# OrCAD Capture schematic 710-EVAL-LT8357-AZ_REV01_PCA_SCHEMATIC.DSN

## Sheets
1 PAGE1
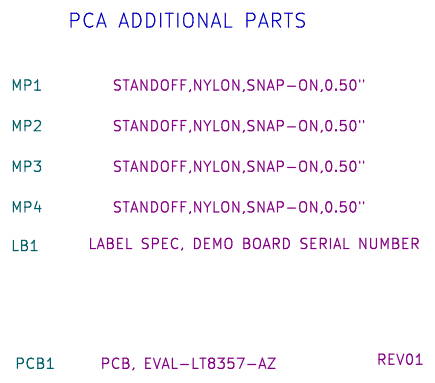
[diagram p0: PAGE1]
2 LT8357EMSE: size Custom; note: 60V LOW-IQ BOOST CONTROLLER
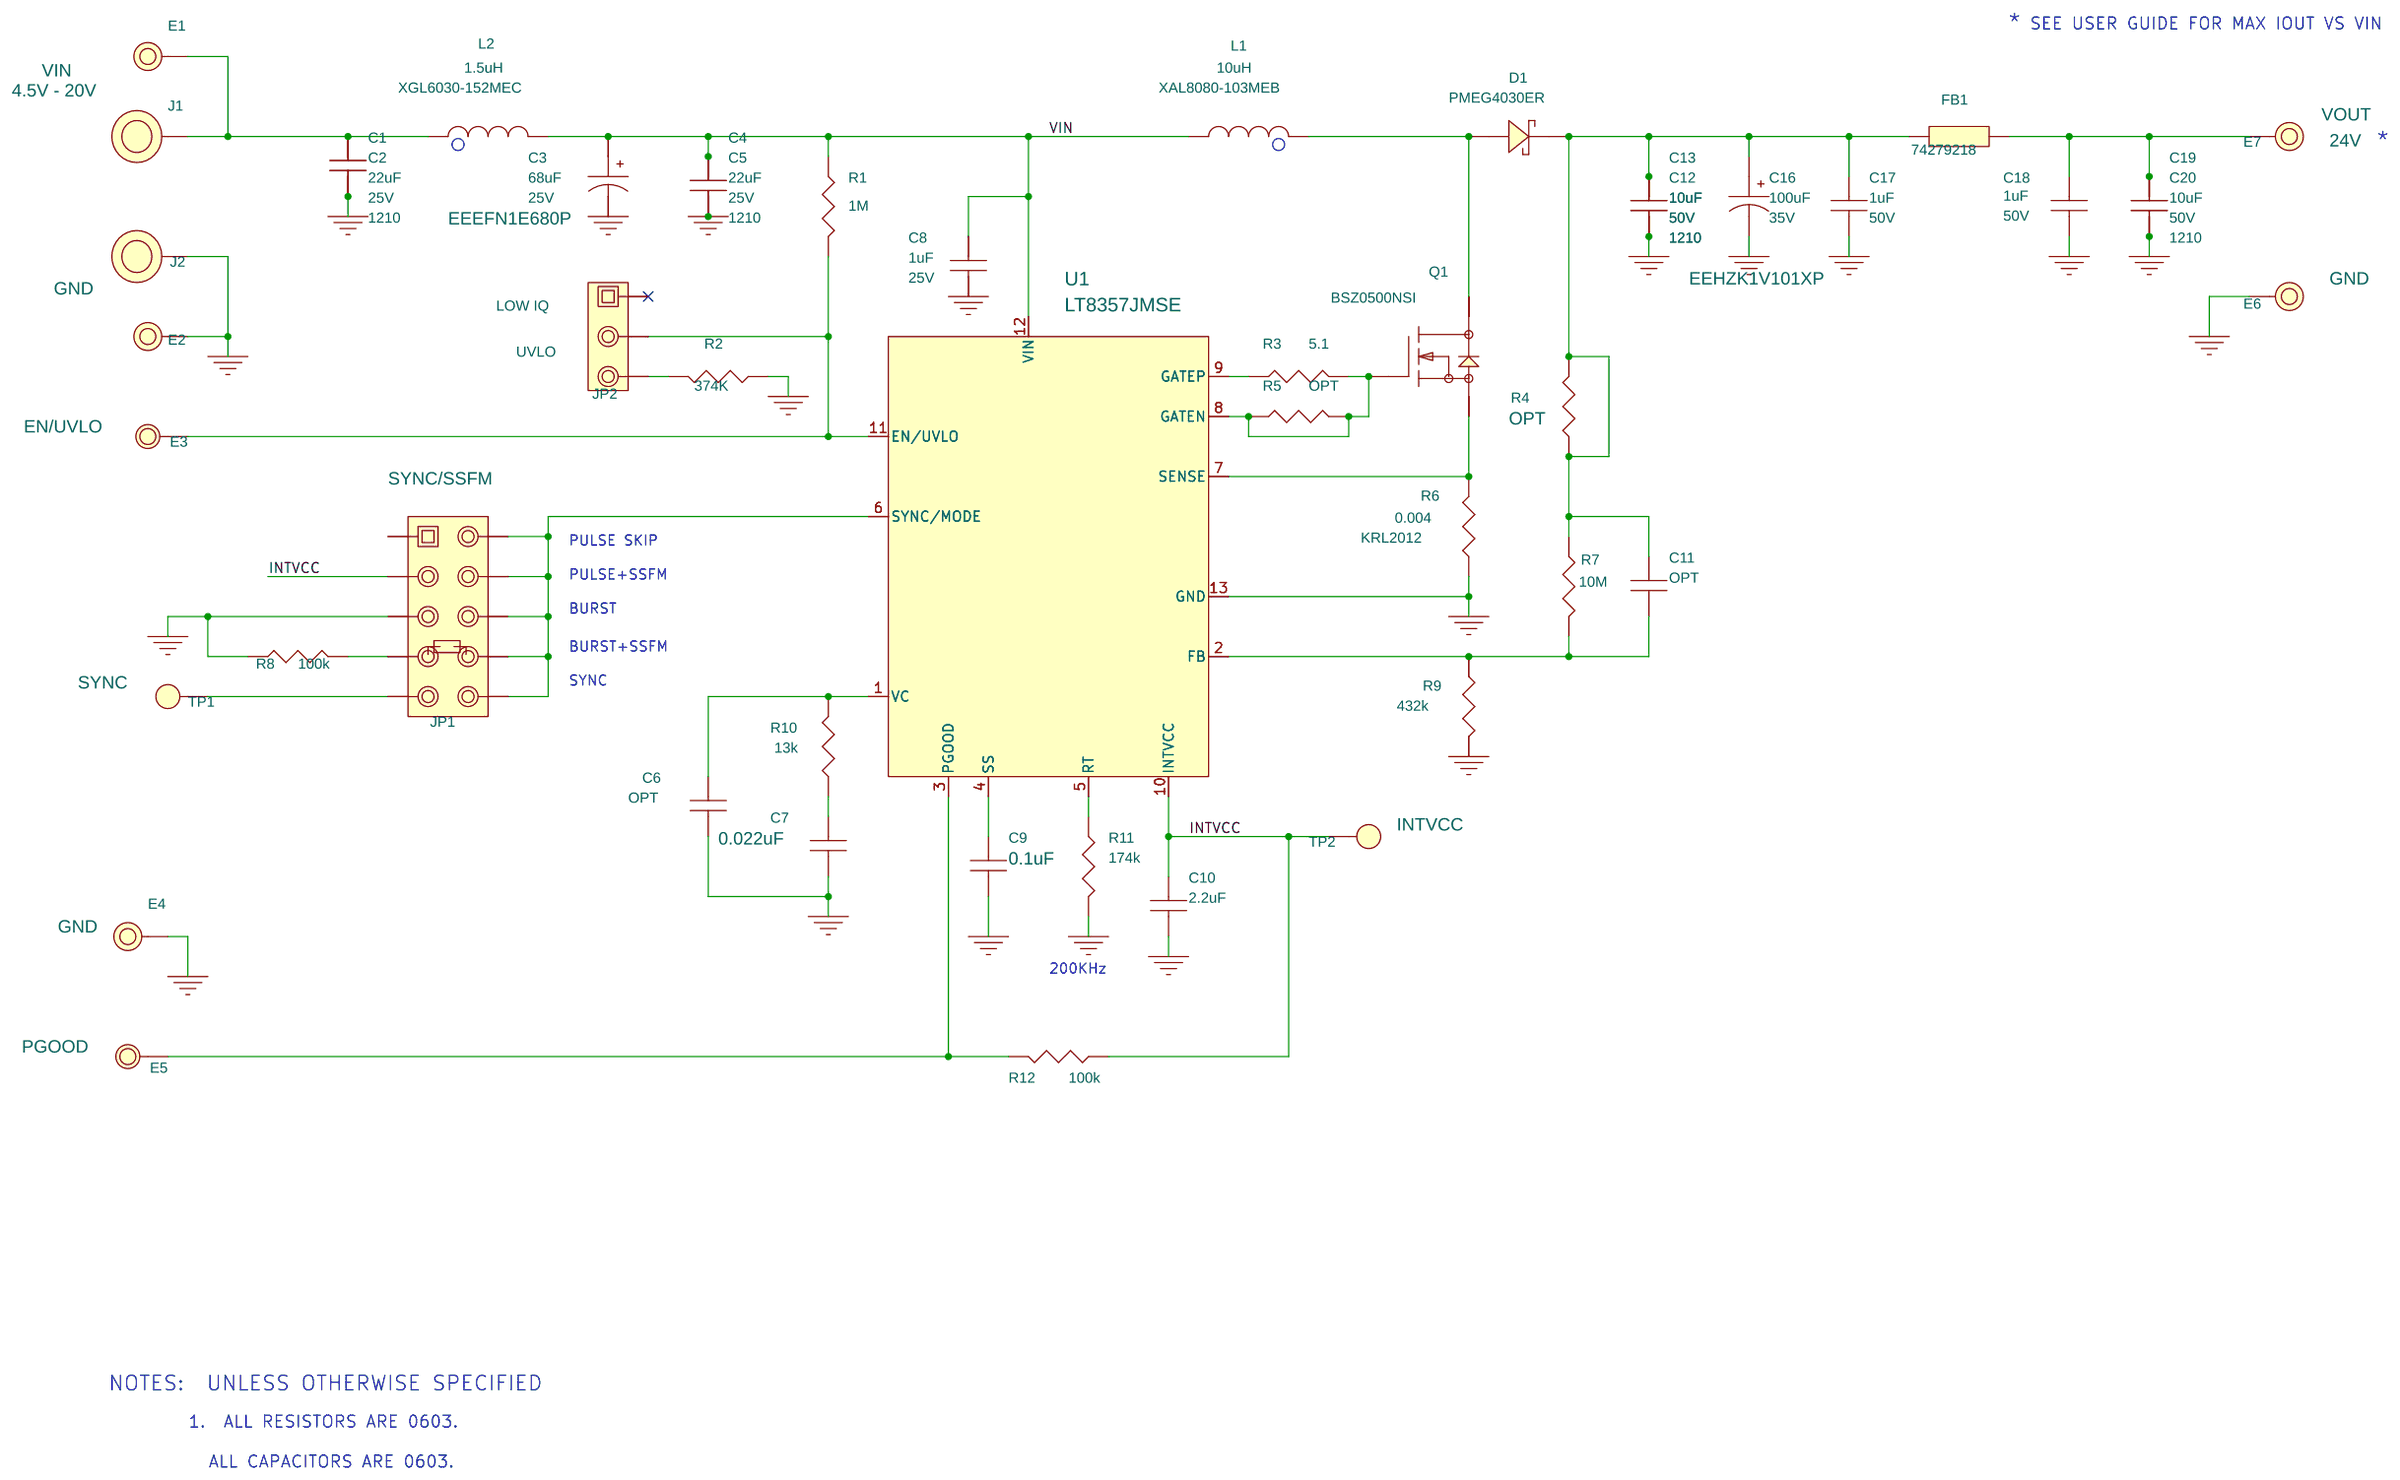
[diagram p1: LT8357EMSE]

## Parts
sheet LT8357EMSE
C1  22uF  [CC1210N]
C2  22uF  [CC1210N]
C3  68uF  [PANASONIC_FN_6.3X5.8]
C4  22uF  [CC1210N]
C5  22uF  [CC1210N]
C6  OPT  [CC0603N]
C7  0.022uF  [CC0603N]
C8  1uF  [CC0603N]
C9  0.1uF  [CC0603N]
C10  2.2uF  [CC0603N]
C11  OPT  [CC0603N]
C12  10uF  [CC1210N]
C13  10uF  [CC1210N]
C16  100uF  [PANASONIC_ZK_6.3X7.7]
C17  1uF  [CC0603N]
C18  1uF  [CC0603N]
C19  10uF  [CC1210N]
C20  10uF  [CC1210N]
D1  PMEG4030ER  [SOD-123W-N]
E1  TEST POINT  [MILLMAX2501]
E2  TEST POINT  [MILLMAX2501]
E3  TEST POINT  [MILLMAX2308]
E4  TEST POINT  [MILLMAX2501]
E5  TEST POINT  [MILLMAX2308]
E6  TEST POINT  [MILLMAX2501]
E7  TEST POINT  [MILLMAX2501]
FB1  600 OHMS @100MHz  [IND1206N]
J1  BANANA JACK  [KEY-575-4]
J2  BANANA JACK  [KEY-575-4]
JP1  HDR  [HD2X5-079]
JP2  HDR.  [HD1X3-079]
L1  10uH  [COILCRAFT-XAL8080]
L2  1.5uH  [COILCRAFT-XGL6030]
Q1  BSZ0500NSI  [INFINEON-PG-TSDSON-8-FL]
R1  1M  [CR0603N]
R2  374K  [CR0603N]
R3  5.1  [CR0603N]
R4  OPT  [CR0603N]
R5  OPT  [CR0603N]
R6  0.004  [SUSUMU-KRL2012]
R7  10M  [CR0603N]
R8  100k  [CR0603N]
R9  432k  [CR0603N]
R10  13k  [CR0603N]
R11  174k  [CR0603N]
R12  100k  [CR0603N]
TP1  TEST PAD  [PADSTYLE1]
TP2  TEST PAD  [PADSTYLE1]
U1  LT8357JMSE  [LTC-MSOP-12-1666]
XJP1  SHUNT
XJP2  SHUNT
sheet PAGE1
LB1  LABEL  [895-0154_REV01]
MP1  STANDOFF  [KEYSTONE_8829-8834]
MP2  STANDOFF  [KEYSTONE_8829-8834]
MP3  STANDOFF  [KEYSTONE_8829-8834]
MP4  STANDOFF  [KEYSTONE_8829-8834]
PCB1  PCB, EVAL-LT8357-AZ

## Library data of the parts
C1 C2 C4 C5 = CAP: CAP.,22uF,X7R,25V,20%,1210,AEC-Q200; CLASS: DISCRETE; Dielectric Type: X7R; FPLIST: CC1210N,CC1210L,CC1210M; Inventory Qty: 2730; Manufacturer: TAIYO YUDEN; Manufacturer PN: TMK325B7226MMHP; PART_NUMBER: 150-1664; Package Size: 1210; Rated Voltage: 25V; Tolerance: 20%
C3 = CAP_P_ALT: CAP.,68uF,ALUM ELECT,25V,20%,6.3x5.8mm,RADIAL,SMD,AEC-Q200; CLASS: DISCRETE; Dielectric Type: ALUM ELECT; FPLIST: PANASONIC_FN_6.3X5.8,PANASONIC_FN_6-3X5-8; Inventory Qty: 0; Manufacturer: PANASONIC; Manufacturer PN: EEEFN1E680P; PART_NUMBER: 150-1872; Package Size: 6.3x5.8mm,RADIAL,SMD; Package Type: Surface Mount; Rated Voltage: 25V; Tolerance: 20%
C6 = CAP: CAP., OPTION, 0603; 1ST FIELD PART: TBD; CLASS: DISCRETE; FPLIST: CC0603N,CC0603L,CC0603M; PART_NUMBER: 150-3038; Package Size: 0603; Package Type: SMD
C7 = CAP: CAP.,0.022uF,X7R,25V,10%,0603,AEC-Q200; CLASS: DISCRETE; Dielectric Type: X7R; FPLIST: CC0603N,CC0603L,CC0603M; Inventory Qty: 0; Manufacturer: KEMET; Manufacturer PN: C0603C223K3RACAUTO; PART_NUMBER: 150-1867; Package Size: 0603; Rated Voltage: 25V; Tolerance: 10%
C8 = CAP: CAP.,1uF,X7R,25V,10%,0603,AEC-Q200; CLASS: DISCRETE; Dielectric Type: X7R; FPLIST: CC0603N,CC0603L,CC0603M; Inventory Qty: 53700; Manufacturer: MURATA; Manufacturer PN: GCM188R71E105KA64D; PART_NUMBER: 150-0291; Package Size: 0603; Rated Voltage: 25V; Tolerance: 10%
C9 = CAP: CAP.,0.1uF,X7R,50V,10%,0603,AEC-Q200; 1ST FIELD PART: TBD; CLASS: DISCRETE; Dielectric Type: X7R; FPLIST: CC0603N,CC0603L,CC0603M; Inventory Qty: 20275; Manufacturer: TDK; Manufacturer PN: CGA3E2X7R1H104K080AA; PART_NUMBER: 150-0514; Package Size: 0603; Rated Voltage: 50V; Tolerance: 10%
C10 = CAP: CAP.,2.2uF,X5R,16V,10%,0603,AEC-Q200; CLASS: DISCRETE; Dielectric Type: X5R; FPLIST: CC0603N,CC0603L,CC0603M; Inventory Qty: 0; Manufacturer: TAIYO YUDEN; Manufacturer PN: EMK107ABJ225KAHT; PART_NUMBER: 150-1868; Package Size: 0603; Package Type: SMD; Rated Voltage: 16V; Temperature Coefficient: X5R; Tolerance: 10%
C11 = CAP: CAP., OPTION, 0603; CLASS: DISCRETE; FPLIST: CC0603N,CC0603L,CC0603M; PART_NUMBER: 150-3038; Package Size: 0603; Package Type: SMD
C12 C13 C19 C20 = CAP: CAP.,10uF,X7S,50V,10%,1210,AEC-Q200, NO SUBS ALLOWED; CLASS: DISCRETE; Dielectric Type: X7S; FPLIST: CC1210N,CC1210L,CC1210M; Inventory Qty: 10520; Manufacturer: MURATA; Manufacturer PN: GCM32EC71H106KA03L; PART_NUMBER: 150-2354; Package Size: 1210; Rated Voltage: 50V; Tolerance: 10%
C16 = CAP_P_ALT: CAP.,100uF,ALUM,35V,20%,SMD,AEC-Q200; CLASS: DISCRETE; Dielectric Type: ALUM; FPLIST: PANASONIC_ZK_6.3X7.7,PANASONIC_ZK_6-3X7-7; Inventory Qty: 0; Manufacturer: PANASONIC; Manufacturer PN: EEHZK1V101XP; PART_NUMBER: 150-1440; Package Size: SMD; Rated Voltage: 35V; Tolerance: 20%
C17 C18 = CAP: CAP.,1uF,X5R,50V,10%,0603,AEC-Q200; CLASS: DISCRETE; Dielectric Type: X5R; FPLIST: CC0603N,CC0603L,CC0603M; Inventory Qty: 52068; Manufacturer: TAIYO YUDEN; Manufacturer PN: UMK107ABJ105KAHT; PART_NUMBER: 150-2446; Package Size: 0603; Package Type: SMD; Rated Voltage: 50V; Tolerance: 10%
D1 = DIODE_SCHOTTKY_A_ALT: DIODE,SCHOTTKY,40V,3A,SOD-123W,AEC-Q101; CLASS: DISCRETE; FPLIST: SOD-123W-N,SOD-123W-L,SOD-123W-M; Inventory Qty: 0; Manufacturer: NEXPERIA; Manufacturer PN: PMEG4030ER,115; PART_NUMBER: 210-0575; Package Size: SOD-123W; Package Type: SOD-123W; Rated Voltage or Zener Voltage: 40V
E1 = TESTPOINT_.219_MILL-MAX_2501: TEST POINT,TURRET,0.094" MTG. HOLE,PCB 0.062" THK; CLASS: IO; FPLIST: MILLMAX2501,MILLMAX2501_ALT1; Inventory Qty: 823526; Manufacturer: MILL-MAX; Manufacturer PN: 2501-2-00-80-00-00-07-0; PART_NUMBER: 260-0003; Part_Field_01: VIN
E2 E4 E6 = TESTPOINT_.219_MILL-MAX_2501: TEST POINT,TURRET,0.094" MTG. HOLE,PCB 0.062" THK; CLASS: IO; FPLIST: MILLMAX2501,MILLMAX2501_ALT1; Inventory Qty: 823526; Manufacturer: MILL-MAX; Manufacturer PN: 2501-2-00-80-00-00-07-0; PART_NUMBER: 260-0003; Part_Field_01: GND
E3 = TEST_POINT_.156_MILL-MAX_2308_A: TEST POINT,TURRET,0.064" MTG. HOLE,PCB 0.062" THK; CLASS: IO; FPLIST: MILLMAX2308,MILLMAX2308-2; Inventory Qty: 1142083; Manufacturer: MILL-MAX; Manufacturer PN: 2308-2-00-80-00-00-07-0; PART_NUMBER: 260-0004; Part_Field_01: EN/UVLO
E5 = TEST_POINT_.156_MILL-MAX_2308_A: TEST POINT,TURRET,0.064" MTG. HOLE,PCB 0.062" THK; CLASS: IO; FPLIST: MILLMAX2308,MILLMAX2308-2; Inventory Qty: 1142083; Manufacturer: MILL-MAX; Manufacturer PN: 2308-2-00-80-00-00-07-0; PART_NUMBER: 260-0004; Part_Field_01: PGOOD
E7 = TESTPOINT_.219_MILL-MAX_2501: TEST POINT,TURRET,0.094" MTG. HOLE,PCB 0.062" THK; CLASS: IO; FPLIST: MILLMAX2501,MILLMAX2501_ALT1; Inventory Qty: 823526; Manufacturer: MILL-MAX; Manufacturer PN: 2501-2-00-80-00-00-07-0; PART_NUMBER: 260-0003; Part_Field_01: VOUT; Part_Field_02: 24V
FB1 = FERRITEBEAD_ALT1: IND.,600 OHMS @100MHz,FERRITE BEAD,25%,2A,100mOHMS,1206; CLASS: DISCRETE; FPLIST: IND1206N,IND1206L,IND1206M; Inventory Qty: 0; Manufacturer: WURTH ELEKTRONIK; Manufacturer PN: 74279218; PART_NUMBER: 200-0874; Package Size: 1206; Tolerance: 25%
J1 = BANANA_KEYSTONE-575-4: CONN.,BANANA JACK,FEMALE,THT,NON-INSULATED,SWAGE,0.218"; CLASS: IO; Inventory Qty: 203061; Manufacturer: KEYSTONE; Manufacturer PN: 575-4; PART_NUMBER: 250-0428; Part_Field_01: VIN; Part_Field_02: 4.5V - 20V
J2 = BANANA_KEYSTONE-575-4: CONN.,BANANA JACK,FEMALE,THT,NON-INSULATED,SWAGE,0.218"; CLASS: IO; Inventory Qty: 203061; Manufacturer: KEYSTONE; Manufacturer PN: 575-4; PART_NUMBER: 250-0428; Part_Field_01: GND
JP1 = HDR2X5_ALT1: CONN.,HDR,MALE,2x5,2mm,VERT,ST,THT; 1ST PART FIELD: SYNC/SSFM; CLASS: IO; Inventory Qty: 246; Manufacturer: WURTH ELEKTRONIK; Manufacturer PN: 62001021121; PART_NUMBER: 250-0679
JP2 = HDR1X3_ALT1: CONN.,HDR.,MALE,1x3,2mm,VERT,ST,THT; 11th Part Field: UVLO; 9th Part Field: LOW IQ; CLASS: IO; Inventory Qty: 219994; Manufacturer: SULLINS CONNECTOR SOLUTIONS; Manufacturer PN: NRPN031PAEN-RC; PART_NUMBER: 250-0418
L1 = IND: IND.,10uH,POWER,20%,8.7A,23.1mOhms,8.8mmX 8.3mm; CLASS: DISCRETE; Inventory Qty: 1230; Manufacturer: COILCRAFT; Manufacturer PN: XAL8080-103MEB; PART_NUMBER: 200-0570; Package Size: 8.8mmX 8.3mm; Tolerance: 20%
L2 = IND: IND.,1.5uH,PWR,SHIELDED,20%,15A,7.3mOHMS,1206,AEC-Q200; CLASS: DISCRETE; Inventory Qty: 0; Manufacturer: COILCRAFT; Manufacturer PN: XGL6030-152MEC; PART_NUMBER: 200-0875; Package Size: 1206; Tolerance: 20%
Q1 = 8P_N-CH_TYPE1D: XSTR.,MOSFET,N-CH,30V,40A,TSDSON-8 FL; CLASS: DISCRETE; Inventory Qty: 1000; Manufacturer: INFINEON; PART_NUMBER: 240-0470; Package Type: TSDSON-8 FL; Rated Voltage: 30V
R1 = RES: RES.,1M OHM,1%,1/10W,0603,AEC-Q200; CLASS: DISCRETE; FPLIST: CR0603N,CR0603L,CR0603M; Inventory Qty: 165718; Manufacturer: VISHAY; Manufacturer PN: CRCW06031M00FKEA; PART_NUMBER: 100-0335; Package Size: 0603; Rated Power: 1/10W; Temperature Coefficient: 100ppm; Tolerance: 1%
R2 = RES: RES.,374k OHMS,1%,1/10W,0603,AEC-Q200; CLASS: DISCRETE; FPLIST: CR0603N,CR0603L,CR0603M; Inventory Qty: 15605; Manufacturer: PANASONIC; Manufacturer PN: ERJ3EKF3743V; PART_NUMBER: 100-0599; Package Size: 0603; Rated Power: 1/10W; Temperature Coefficient: 100pp,; Tolerance: 1%
R3 = RES: RES.,5.1 OHMS,1%,1/10W,0603,AEC-Q200; CLASS: DISCRETE; FPLIST: CR0603N,CR0603L,CR0603M; Inventory Qty: 19380; Manufacturer: VISHAY; Manufacturer PN: CRCW06035R10FKEA; PART_NUMBER: 100-1133; Package Size: 0603; Rated Power: 1/10W; Temperature Coefficient: 100ppm; Tolerance: 1%
R4 = RES: RES., OPTION, 0603; 1ST FIELD PART: TBD; CLASS: DISCRETE; FPLIST: CR0603N,CR0603L,CR0603M; PART_NUMBER: 100-2374; Package Size: 0603
R5 = RES: RES., OPTION, 0603; CLASS: DISCRETE; FPLIST: CR0603N,CR0603L,CR0603M; PART_NUMBER: 100-2374; Package Size: 0603
R6 = RES: RES.,0.004 OHM,1%,1W,0805,LONG-SIDE TERM,SENSE,AEC-Q200; 1st_Part_Field: KRL2012; CLASS: DISCRETE; Inventory Qty: 0; Manufacturer: SUSUMU; Manufacturer PN: KRL2012E-M-R004-F-T5; PART_NUMBER: 100-1838; Package Size: 0805,LONG-SIDE TERM; Rated Power: 1W; Temperature Coefficient: +/-50ppm; Tolerance: 1%
R7 = RES: RES.,10M OHMS,1%,1/10W,0603,AEC-Q200; CLASS: DISCRETE; FPLIST: CR0603N,CR0603L,CR0603M; Inventory Qty: 15800; Manufacturer: PANASONIC; Manufacturer PN: ERJ3EKF1005V; PART_NUMBER: 100-2709; Package Size: 0603; Rated Power: 1/10W; Temperature Coefficient: 100ppm/C; Tolerance: 1%
R8 R12 = RES: RES.,100k OHMS,1%,1/10W,0603,AEC-Q200; CLASS: DISCRETE; FPLIST: CR0603N,CR0603L,CR0603M; Inventory Qty: 185604; Manufacturer: VISHAY; Manufacturer PN: CRCW0603100KFKEA; PART_NUMBER: 100-0343; Package Size: 0603; Rated Power: 1/10W; Temperature Coefficient: +/-100ppm; Tolerance: 1%
R9 = RES: RES.,432k OHMS,1%,1/10W,0603,AEC-Q200; CLASS: DISCRETE; FPLIST: CR0603N,CR0603L,CR0603M; Inventory Qty: 220; Manufacturer: NIC; Manufacturer PN: NRC06F4323TRF; PART_NUMBER: 100-2848; Package Size: 0603; Rated Power: 1/10W; Temperature Coefficient: 100ppm; Tolerance: 1%
R10 = RES: RES.,13k OHMS,1%,1/10W,0603,AEC-Q200; CLASS: DISCRETE; FPLIST: CR0603N,CR0603L,CR0603M; Inventory Qty: 178; Manufacturer: VISHAY; Manufacturer PN: CRCW060313K0FKEA; PART_NUMBER: 100-0854; Package Size: 0603; Rated Power: 1/10W; Temperature Coefficient: 100ppm; Tolerance: 1%
R11 = RES: RES.,174k OHMS,1%,1/10W,0603,AEC-Q200; CLASS: DISCRETE; FPLIST: CR0603N,CR0603L,CR0603M; Inventory Qty: 0; Manufacturer: PANASONIC; Manufacturer PN: ERJ3EKF1743V; PART_NUMBER: 100-1839; Package Size: 0603; Rated Power: 1/10W; Temperature Coefficient: +/-100ppm; Tolerance: 1%
TP1 = PAD_STYLE_C: TESTPOINT, PCB COPPER FEATURE; CLASS: IO; FPLIST: PADSTYLE1,PADSTYLE2,PADSTYLE3,PADSTYLE4,PADSTYLE5,PADSTYLE6,PADSTYLE7,PADSTYLE8; Manufacturer: N/A; Manufacturer PN: N/A; Part_Field_01: SYNC
TP2 = PAD_STYLE_C: TESTPOINT, PCB COPPER FEATURE; CLASS: IO; FPLIST: PADSTYLE1,PADSTYLE2,PADSTYLE3,PADSTYLE4,PADSTYLE5,PADSTYLE6,PADSTYLE7,PADSTYLE8; Manufacturer: N/A; Manufacturer PN: N/A; Part_Field_01: INTVCC
U1 = LT8357-MSE_4: IC,CURRENT MODE,DC/DC CONTROLLER,WIDE INPUT RANGE,MSOP-12; CLASS: IC; Inventory Qty: 0; Manufacturer: ANALOG DEVICES; Manufacturer PN: LT8357JMSE#PBF; PART_NUMBER: LT8357JMSE#PBF; Package Size: 12-MSOP; Package Type: MSOP-12
XJP1 XJP2 = SHUNT_2MM_C: CONN.,SHUNT,FEMALE,2 POS,2mm; CLASS: IO; Inventory Qty: 64675; Manufacturer: Wurth Elektronik; Manufacturer PN: 60800213421; PART_NUMBER: 250-0485
LB1 = BLANK_LABEL: LABEL SPEC, DEMO BOARD SERIAL NUMBER; Inventory Qty: 0; Manufacturer: BRADY; Manufacturer PN: THT-96-717-10; PART_NUMBER: 895-0154
MP1-MP4 = BLANK_MECHANICAL_PART: STANDOFF,NYLON,SNAP-ON,0.50"; CLASS: DISCRETE; Inventory Qty: 214842; Manufacturer: KEYSTONE; Manufacturer PN: 8833; PART_NUMBER: 763-0007
PCB1 = BLANK_PCB_PART: BOM Notes: REV01; CLASS: DISCRETE; Inventory Qty: 0; Manufacturer: ADI APPROVED SUPPLIER; Manufacturer PN: 600-EVAL-LT8357-AZ; PART_NUMBER: 600-EVAL-LT8357-AZ

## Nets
GND: C1.2 C2.2 C3.2 C4.2 C5.2 C6.2 C7.2 C8.2 C9.2 C10.2 C12.2 C13.2 C16.2 C17.2 C18.2 C19.2 C20.2 E2.1 E4.1 E6.1 J2.1 JP1.5 R2.1 R6.2 R8.2 R9.1 R11.2 U1.13(GND)
VIN: C3.1 C4.1 C5.1 C8.1 L1.2 L2.2 R1.1 U1.12(VIN)
INTVCC: C10.1 JP1.3 R12.1 TP2.1 U1.10(INTVCC)
N1229433: JP1.2 JP1.4 JP1.6 JP1.8 JP1.10 U1.6(SYNC/MODE)
N1232161: C9.1 U1.4(SS)
N1232739: R11.1 U1.5(RT)
N1234611: D1.2(A) L1.1 Q1.5(D) Q1.6(D) Q1.7(D) Q1.8(D)
N1235307: C11.1 C12.1 C13.1 C16.1 C17.1 D1.1(C) FB1.1 R4.1 R4.2 R7.2
N1236981: C11.2 R7.1 R9.2 U1.2(FB)
N1243361: E5.1 R12.2 U1.3(PGOOD)
N1243835: Q1.4(G) R3.2 R5.1 R5.2 U1.8(GATEN)
N1252479: Q1.1(S) Q1.2(S) Q1.3(S) R6.1 U1.7(SENSE)
N1303899: C6.1 R10.1 U1.1(VC)
N1322099: E3.1 JP2.2 R1.2 U1.11(EN/UVLO)
N1343937: C7.1 R10.2
N1346107: C1.1 C2.1 E1.1 J1.1 L2.1
N1353373: R3.1 U1.9(GATEP)
N1358538: C18.1 C19.1 C20.1 E7.1 FB1.2
N1379196: JP1.7 R8.1
N1379214: JP1.9 TP1.1
N1396301: JP2.3 R2.2

Not connected (* = marked no-connect by the designer): JP1 1; JP2 1*

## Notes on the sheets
sheet 1
- PCA ADDITIONAL PARTS
sheet 2
- *
- SEE USER GUIDE FOR MAX IOUT VS VIN
- *
- PULSE SKIP
- PULSE+SSFM
- BURST
- BURST+SSFM
- SYNC
- 200KHz
- NOTES:  UNLESS OTHERWISE SPECIFIED
- 1.  ALL RESISTORS ARE 0603.
- ALL CAPACITORS ARE 0603.
